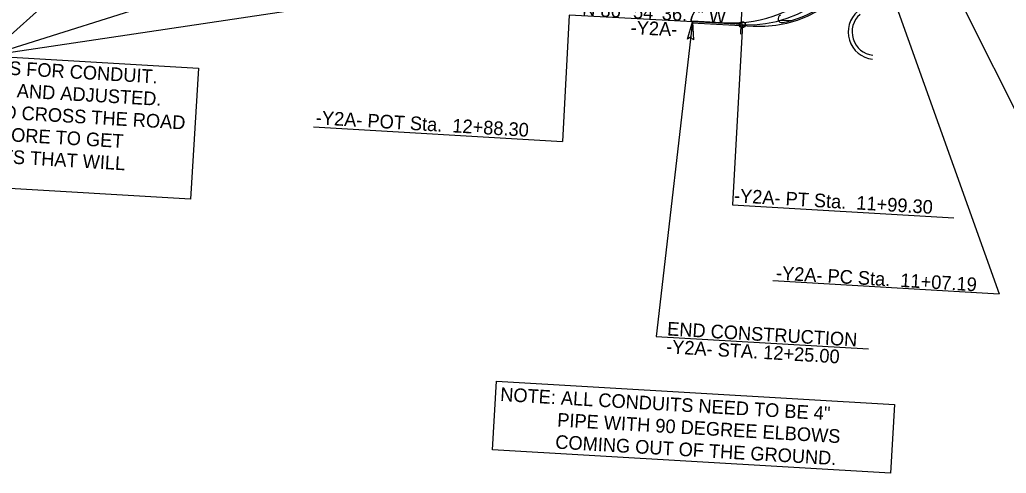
# Model space of a CAD drawing. Extents: x 2010838 to 2015151, y 441905 to 447792.
# Drawn here: x 2012745 to 2013251, y 444527 to 444760 of the extents above; entities that cross this region are included whole.
import ezdxf

# ---------------------------------------------------------------- set-up
doc = ezdxf.new("R2010")
doc.units = 0
for name, color, linetype in [('A-Wall-Blow', 7, 'Continuous'), ('C-Alignment Geometry', 7, 'Continuous'), ('C-Building', 7, 'Continuous'), ('C-Grave Plots', 7, 'Continuous'), ('CLRD', 7, 'Continuous'), ('Cont-2-Lidar', 7, 'Continuous'), ('Default_10ft_LIDAR_Contou', 7, 'Continuous'), ('Default_2FT_LIDAR_Contour', 7, 'Continuous'), ('s-Existing Major', 7, 'Continuous'), ('S-Existing Minor', 7, 'Continuous'), ('S-overhead electric', 7, 'Continuous'), ('TEXT-MED', 7, 'Continuous')]:
    doc.layers.add(name, color=color, linetype=linetype)

msp = doc.modelspace()

# ---------------------------------------------------------------- linework, layer by layer
at = {"layer": 'A-Wall-Blow'}
msp.add_line((2013115.58, 444767.76), (2013115, 444757.13), dxfattribs=at)
at = {"layer": 'C-Alignment Geometry'}
msp.add_line((2013134.19, 444759.38), (2013141.04, 444759.29), dxfattribs=at)
for centre, radius, start, end in [((2013124.54, 444816.2), 59.25, 281.6024, 321.882), ((2013136.05, 444760.12), 2, 111.9588, 281.6024)]:
    msp.add_arc(centre, radius, start, end, dxfattribs=at)
at = {"layer": 'C-Building'}
msp.add_line((2013115, 444757.13), (2013114.73, 444752.13), dxfattribs=at)
at = {"layer": 'CLRD'}
msp.add_line((2013115.7, 444757.09), (2013026.83, 444761.88), dxfattribs=at)
msp.add_arc((2013118.93, 444817), 60, 266.9102, 354.8697, dxfattribs=at)
at = {"layer": 'Default_10ft_LIDAR_Contou'}
for p, q in [((2013182.91, 444858.64), (2013267.89, 444688.86)), ((2013178.69, 444811.64), (2013247.53, 444618.89)), ((2013026.83, 444761.88), (2013023.34, 444697.12)), ((2013115.7, 444757.09), (2013110.71, 444664.63)), ((2012895.42, 444704.66), (2013023.34, 444697.12)), ((2013110.71, 444664.63), (2013224.37, 444657.93)), ((2013131.31, 444625.74), (2013247.53, 444618.89))]:
    msp.add_line(p, q, dxfattribs=at)
msp.add_circle((2013115.7, 444757.09), 1.5, dxfattribs=at)
at = {"layer": 's-Existing Major'}
msp.add_lwpolyline([(2013087.45, 444749.71), (2013090.04, 444758.47), (2013090.58, 444749.3), (2013089.12, 444750.63)], close=True, dxfattribs=at)
at = {"layer": 'S-Existing Minor'}
for p, q in [((2012728, 444741.11), (2013187.7, 445155.34)), ((2012728, 444741.11), (2013407.25, 444954.8)), ((2012728, 444741.11), (2013122.55, 444800.21)), ((2013090.04, 444758.47), (2013071.41, 444596.98)), ((2013071.41, 444596.98), (2013180.51, 444590.54))]:
    msp.add_line(p, q, dxfattribs=at)
for points in [[(2012635.51, 444746.56), (2012836.29, 444734.73), (2012832.33, 444667.52), (2012631.55, 444679.36)], [(2012989.37, 444574.03), (2013193.87, 444561.97), (2013191.79, 444526.7), (2012987.29, 444538.76)]]:
    msp.add_lwpolyline(points, close=True, dxfattribs=at)
at = {"layer": 'S-overhead electric'}
for p, q in [((2013090.01, 444757.97), (2013121.3, 444756.28)), ((2013090.07, 444758.97), (2013107.98, 444758))]:
    msp.add_line(p, q, dxfattribs=at)
for centre, radius, start, end in [((2013124.54, 444816.2), 60, 266.9102, 353.5264), ((2013110.72, 444822.95), 65, 266.9102, 316.6324), ((2013184.05, 444753.33), 14, 131.0732, 263.7653)]:
    msp.add_arc(centre, radius, start, end, dxfattribs=at)
at = {"layer": 'TEXT-MED'}
msp.add_arc((2013184.05, 444753.33), 12, 131.0732, 263.7653, dxfattribs=at)

# ---------------------------------------------------------------- texts
at = {"layer": 'C-Grave Plots'}
for s, p in [('END CONSTRUCTION', (2013076.93, 444597.51)), ('-Y2A- STA. 12+25.00', (2013076.39, 444588.35))]:
    msp.add_text(s, height=7, rotation=356.6264, dxfattribs=at).set_placement(p)
at = {"layer": 'Cont-2-Lidar'}
msp.add_text('N 86%%d 54\' 36.7" W', height=7, rotation=356.9102, dxfattribs=at).set_placement((2013033.37, 444761.73))
at = {"layer": 'Default_10ft_LIDAR_Contou'}
for s, p in [('-Y2A- POT Sta.  12+88.30', (2012896.49, 444705.92)), ('-Y2A- PT Sta.  11+99.30', (2013111.26, 444665.89)), ('-Y2A- PC Sta.  11+07.19', (2013132.82, 444626.19))]:
    msp.add_text(s, height=7, rotation=356.6264, dxfattribs=at).set_placement(p)
at = {"layer": 'Default_2FT_LIDAR_Contour'}
msp.add_text('-Y2A-', height=7, rotation=357.6857, dxfattribs=at).set_placement((2013058.23, 444752.13))
at = {"layer": 'S-Existing Minor'}
for s, p in [('PROPOSED LOCATIONS FOR CONDUIT.', (2012635.56, 444737.46)), ('THESE CAN BE MOVED AND ADJUSTED.', (2012634.89, 444726.11)), ('THIS IS FOR POWER TO CROSS THE ROAD', (2012634.22, 444714.75)), ('WITHOUT HAVING TO BORE TO GET', (2012633.55, 444703.4)), ('SERVICE TO THE LIGHTS THAT WILL', (2012632.88, 444692.04)), ('NOTE: ALL CONDUITS NEED TO BE 4" ', (2012991.2, 444563.86)), ('PIPE WITH 90 DEGREE ELBOWS ', (2013020.47, 444550.74)), ('COMING OUT OF THE GROUND.', (2013019.47, 444539.4))]:
    msp.add_text(s, height=7, rotation=356.6264, dxfattribs=at).set_placement(p)

doc.saveas('drawing.dxf')
